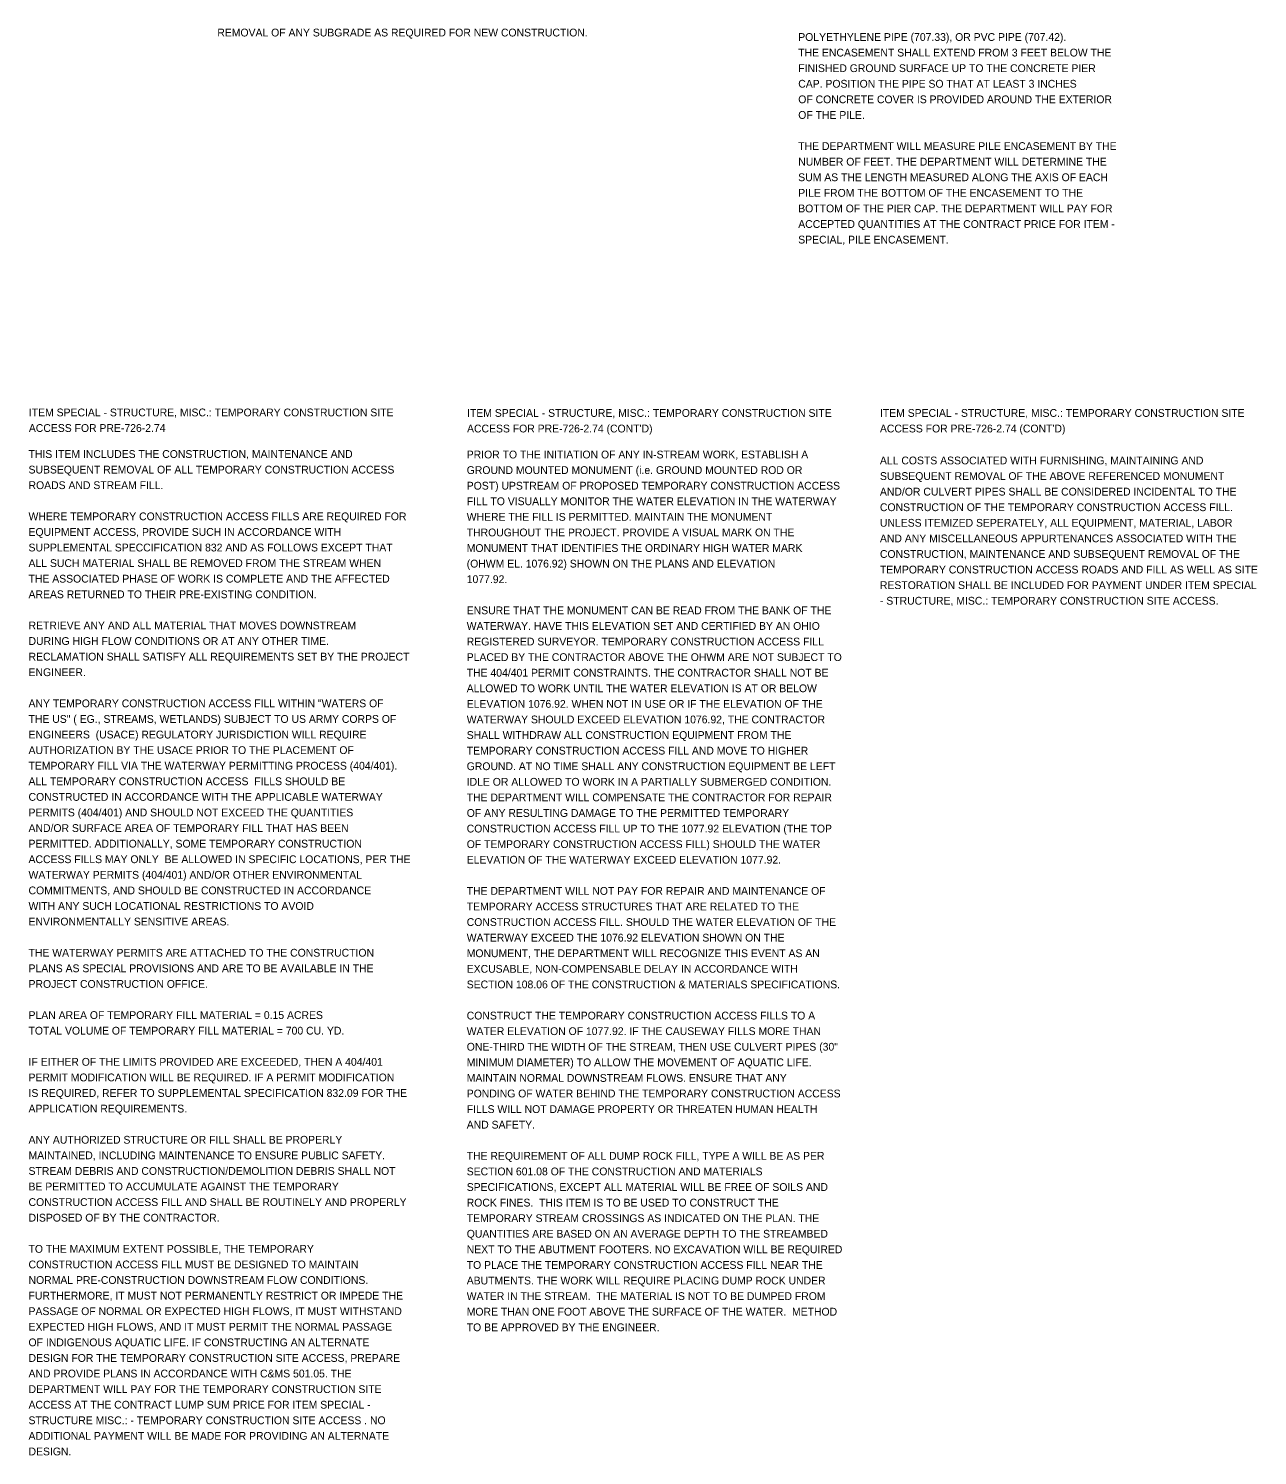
# Model space of a CAD drawing. Extents: x -15 to 144, y -80 to 40.
# Drawn here: x -6.81 to 15.27, y -29.12 to -3.48 of the extents above; entities that cross this region are included whole.
import ezdxf

# ---------------------------------------------------------------- set-up
doc = ezdxf.new("R2010")
doc.units = 0
doc.layers.add('BR_P_Gen_Text', color=7, linetype='Continuous')

msp = doc.modelspace()

# ---------------------------------------------------------------- texts
at = {"layer": 'BR_P_Gen_Text'}
for s, p in [('REMOVAL OF ANY SUBGRADE AS REQUIRED FOR NEW CONSTRUCTION. ', (-3.418, -3.626)), ('POLYETHYLENE PIPE (707.33), OR PVC PIPE (707.42).', (7.022, -3.706)), ('THE ENCASEMENT SHALL EXTEND FROM 3 FEET BELOW THE', (7.022, -3.986)), ('FINISHED GROUND SURFACE UP TO THE CONCRETE PIER', (7.022, -4.266)), ('CAP. POSITION THE PIPE SO THAT AT LEAST 3 INCHES', (7.022, -4.546)), ('OF CONCRETE COVER IS PROVIDED AROUND THE EXTERIOR', (7.022, -4.826)), ('OF THE PILE.', (7.022, -5.106)), ('THE DEPARTMENT WILL MEASURE PILE ENCASEMENT BY THE', (7.022, -5.666)), ('NUMBER OF FEET. THE DEPARTMENT WILL DETERMINE THE', (7.022, -5.946)), ('SUM AS THE LENGTH MEASURED ALONG THE AXIS OF EACH', (7.022, -6.226)), ('PILE FROM THE BOTTOM OF THE ENCASEMENT TO THE', (7.022, -6.506)), ('BOTTOM OF THE PIER CAP. THE DEPARTMENT WILL PAY FOR', (7.022, -6.786)), ('ACCEPTED QUANTITIES AT THE CONTRACT PRICE FOR ITEM -', (7.022, -7.066)), ('SPECIAL, PILE ENCASEMENT.', (7.022, -7.346)), ('ITEM SPECIAL - STRUCTURE, MISC.: TEMPORARY CONSTRUCTION SITE ', (-6.805, -10.451)), ('ITEM SPECIAL - STRUCTURE, MISC.: TEMPORARY CONSTRUCTION SITE ', (1.07, -10.46)), ('ITEM SPECIAL - STRUCTURE, MISC.: TEMPORARY CONSTRUCTION SITE ', (8.49, -10.46)), ('ACCESS FOR PRE-726-2.74', (-6.805, -10.731)), ("ACCESS FOR PRE-726-2.74 (CONT'D) ", (1.07, -10.74)), ("ACCESS FOR PRE-726-2.74 (CONT'D) ", (8.49, -10.74)), ('THIS ITEM INCLUDES THE CONSTRUCTION, MAINTENANCE AND ', (-6.811, -11.198)), ('PRIOR TO THE INITIATION OF ANY IN-STREAM WORK, ESTABLISH A ', (1.064, -11.207)), ('ALL COSTS ASSOCIATED WITH FURNISHING, MAINTAINING AND ', (8.49, -11.314)), ('SUBSEQUENT REMOVAL OF ALL TEMPORARY CONSTRUCTION ACCESS ', (-6.811, -11.478)), ('GROUND MOUNTED MONUMENT (i.e. GROUND MOUNTED ROD OR ', (1.064, -11.487)), ('SUBSEQUENT REMOVAL OF THE ABOVE REFERENCED MONUMENT ', (8.49, -11.594)), ('ROADS AND STREAM FILL. ', (-6.811, -11.758)), ('POST) UPSTREAM OF PROPOSED TEMPORARY CONSTRUCTION ACCESS ', (1.064, -11.767)), ('AND/OR CULVERT PIPES SHALL BE CONSIDERED INCIDENTAL TO THE ', (8.49, -11.874)), ('FILL TO VISUALLY MONITOR THE WATER ELEVATION IN THE WATERWAY ', (1.064, -12.047)), ('CONSTRUCTION OF THE TEMPORARY CONSTRUCTION ACCESS FILL. ', (8.49, -12.154)), ('WHERE TEMPORARY CONSTRUCTION ACCESS FILLS ARE REQUIRED FOR ', (-6.811, -12.318)), ('WHERE THE FILL IS PERMITTED. MAINTAIN THE MONUMENT ', (1.064, -12.327)), ('UNLESS ITEMIZED SEPERATELY, ALL EQUIPMENT, MATERIAL, LABOR ', (8.49, -12.434)), ('EQUIPMENT ACCESS, PROVIDE SUCH IN ACCORDANCE WITH ', (-6.811, -12.598)), ('THROUGHOUT THE PROJECT. PROVIDE A VISUAL MARK ON THE ', (1.064, -12.607)), ('SUPPLEMENTAL SPECCIFICATION 832 AND AS FOLLOWS EXCEPT THAT ', (-6.811, -12.878)), ('MONUMENT THAT IDENTIFIES THE ORDINARY HIGH WATER MARK ', (1.064, -12.887)), ('AND ANY MISCELLANEOUS APPURTENANCES ASSOCIATED WITH THE ', (8.49, -12.714)), ('ALL SUCH MATERIAL SHALL BE REMOVED FROM THE STREAM WHEN ', (-6.811, -13.158)), ('(OHWM EL. 1076.92) SHOWN ON THE PLANS AND ELEVATION', (1.064, -13.167)), ('CONSTRUCTION, MAINTENANCE AND SUBSEQUENT REMOVAL OF THE ', (8.49, -12.994)), ('THE ASSOCIATED PHASE OF WORK IS COMPLETE AND THE AFFECTED ', (-6.811, -13.438)), ('1077.92. ', (1.064, -13.447)), ('TEMPORARY CONSTRUCTION ACCESS ROADS AND FILL AS WELL AS SITE ', (8.49, -13.274)), ('AREAS RETURNED TO THEIR PRE-EXISTING CONDITION.', (-6.811, -13.718)), ('RESTORATION SHALL BE INCLUDED FOR PAYMENT UNDER ITEM SPECIAL ', (8.49, -13.554)), ('- STRUCTURE, MISC.: TEMPORARY CONSTRUCTION SITE ACCESS.', (8.49, -13.834)), ('ENSURE THAT THE MONUMENT CAN BE READ FROM THE BANK OF THE ', (1.064, -14.007)), ('RETRIEVE ANY AND ALL MATERIAL THAT MOVES DOWNSTREAM ', (-6.811, -14.278)), ('WATERWAY. HAVE THIS ELEVATION SET AND CERTIFIED BY AN OHIO ', (1.064, -14.287)), ('DURING HIGH FLOW CONDITIONS OR AT ANY OTHER TIME. ', (-6.811, -14.558)), ('REGISTERED SURVEYOR. TEMPORARY CONSTRUCTION ACCESS FILL ', (1.064, -14.567)), ('RECLAMATION SHALL SATISFY ALL REQUIREMENTS SET BY THE PROJECT ', (-6.811, -14.838)), ('PLACED BY THE CONTRACTOR ABOVE THE OHWM ARE NOT SUBJECT TO ', (1.064, -14.847)), ('ENGINEER.', (-6.811, -15.118)), ('THE 404/401 PERMIT CONSTRAINTS. THE CONTRACTOR SHALL NOT BE ', (1.064, -15.127)), ('ALLOWED TO WORK UNTIL THE WATER ELEVATION IS AT OR BELOW ', (1.064, -15.407)), ('ANY TEMPORARY CONSTRUCTION ACCESS FILL WITHIN "WATERS OF ', (-6.811, -15.678)), ('ELEVATION 1076.92. WHEN NOT IN USE OR IF THE ELEVATION OF THE ', (1.064, -15.687)), ('THE US" ( EG., STREAMS, WETLANDS) SUBJECT TO US ARMY CORPS OF ', (-6.811, -15.958)), ('WATERWAY SHOULD EXCEED ELEVATION 1076.92, THE CONTRACTOR ', (1.064, -15.967)), ('ENGINEERS  (USACE) REGULATORY JURISDICTION WILL REQUIRE ', (-6.811, -16.238)), ('SHALL WITHDRAW ALL CONSTRUCTION EQUIPMENT FROM THE ', (1.064, -16.247)), ('AUTHORIZATION BY THE USACE PRIOR TO THE PLACEMENT OF ', (-6.811, -16.518)), ('TEMPORARY CONSTRUCTION ACCESS FILL AND MOVE TO HIGHER ', (1.064, -16.527)), ('TEMPORARY FILL VIA THE WATERWAY PERMITTING PROCESS (404/401). ', (-6.811, -16.798)), ('GROUND. AT NO TIME SHALL ANY CONSTRUCTION EQUIPMENT BE LEFT ', (1.064, -16.807)), ('ALL TEMPORARY CONSTRUCTION ACCESS  FILLS SHOULD BE ', (-6.811, -17.078)), ('IDLE OR ALLOWED TO WORK IN A PARTIALLY SUBMERGED CONDITION. ', (1.064, -17.087)), ('CONSTRUCTED IN ACCORDANCE WITH THE APPLICABLE WATERWAY ', (-6.811, -17.358)), ('THE DEPARTMENT WILL COMPENSATE THE CONTRACTOR FOR REPAIR ', (1.064, -17.367)), ('PERMITS (404/401) AND SHOULD NOT EXCEED THE QUANTITIES ', (-6.811, -17.638)), ('OF ANY RESULTING DAMAGE TO THE PERMITTED TEMPORARY ', (1.064, -17.647)), ('AND/OR SURFACE AREA OF TEMPORARY FILL THAT HAS BEEN ', (-6.811, -17.918)), ('CONSTRUCTION ACCESS FILL UP TO THE 1077.92 ELEVATION (THE TOP ', (1.064, -17.927)), ('PERMITTED. ADDITIONALLY, SOME TEMPORARY CONSTRUCTION ', (-6.811, -18.198)), ('OF TEMPORARY CONSTRUCTION ACCESS FILL) SHOULD THE WATER ', (1.064, -18.207)), ('ACCESS FILLS MAY ONLY  BE ALLOWED IN SPECIFIC LOCATIONS, PER THE ', (-6.811, -18.478)), ('ELEVATION OF THE WATERWAY EXCEED ELEVATION 1077.92.', (1.064, -18.487)), ('WATERWAY PERMITS (404/401) AND/OR OTHER ENVIRONMENTAL ', (-6.811, -18.758)), ('COMMITMENTS, AND SHOULD BE CONSTRUCTED IN ACCORDANCE ', (-6.811, -19.038)), ('THE DEPARTMENT WILL NOT PAY FOR REPAIR AND MAINTENANCE OF ', (1.064, -19.047)), ('WITH ANY SUCH LOCATIONAL RESTRICTIONS TO AVOID ', (-6.811, -19.318)), ('TEMPORARY ACCESS STRUCTURES THAT ARE RELATED TO THE ', (1.064, -19.327)), ('ENVIRONMENTALLY SENSITIVE AREAS. ', (-6.811, -19.598)), ('CONSTRUCTION ACCESS FILL. SHOULD THE WATER ELEVATION OF THE ', (1.064, -19.607)), ('WATERWAY EXCEED THE 1076.92 ELEVATION SHOWN ON THE ', (1.064, -19.887)), ('THE WATERWAY PERMITS ARE ATTACHED TO THE CONSTRUCTION ', (-6.811, -20.158)), ('MONUMENT, THE DEPARTMENT WILL RECOGNIZE THIS EVENT AS AN ', (1.064, -20.167)), ('PLANS AS SPECIAL PROVISIONS AND ARE TO BE AVAILABLE IN THE ', (-6.811, -20.438)), ('EXCUSABLE, NON-COMPENSABLE DELAY IN ACCORDANCE WITH ', (1.064, -20.447)), ('PROJECT CONSTRUCTION OFFICE. ', (-6.811, -20.718)), ('SECTION 108.06 OF THE CONSTRUCTION & MATERIALS SPECIFICATIONS.', (1.064, -20.727)), ('PLAN AREA OF TEMPORARY FILL MATERIAL = 0.15 ACRES ', (-6.811, -21.278)), ('CONSTRUCT THE TEMPORARY CONSTRUCTION ACCESS FILLS TO A ', (1.064, -21.287)), ('TOTAL VOLUME OF TEMPORARY FILL MATERIAL = 700 CU. YD. ', (-6.811, -21.558)), ('WATER ELEVATION OF 1077.92. IF THE CAUSEWAY FILLS MORE THAN ', (1.064, -21.567)), ('ONE-THIRD THE WIDTH OF THE STREAM, THEN USE CULVERT PIPES (30" ', (1.064, -21.847)), ('IF EITHER OF THE LIMITS PROVIDED ARE EXCEEDED, THEN A 404/401 ', (-6.811, -22.118)), ('MINIMUM DIAMETER) TO ALLOW THE MOVEMENT OF AQUATIC LIFE. ', (1.064, -22.127)), ('PERMIT MODIFICATION WILL BE REQUIRED. IF A PERMIT MODIFICATION ', (-6.811, -22.398)), ('MAINTAIN NORMAL DOWNSTREAM FLOWS. ENSURE THAT ANY ', (1.064, -22.407)), ('IS REQUIRED, REFER TO SUPPLEMENTAL SPECIFICATION 832.09 FOR THE ', (-6.811, -22.678)), ('PONDING OF WATER BEHIND THE TEMPORARY CONSTRUCTION ACCESS ', (1.064, -22.687)), ('APPLICATION REQUIREMENTS.', (-6.811, -22.958)), ('FILLS WILL NOT DAMAGE PROPERTY OR THREATEN HUMAN HEALTH ', (1.064, -22.967)), ('AND SAFETY.', (1.064, -23.247)), ('ANY AUTHORIZED STRUCTURE OR FILL SHALL BE PROPERLY ', (-6.811, -23.518)), ('MAINTAINED, INCLUDING MAINTENANCE TO ENSURE PUBLIC SAFETY. ', (-6.811, -23.798)), ('THE REQUIREMENT OF ALL DUMP ROCK FILL, TYPE A WILL BE AS PER ', (1.064, -23.807)), ('STREAM DEBRIS AND CONSTRUCTION/DEMOLITION DEBRIS SHALL NOT ', (-6.811, -24.078)), ('SECTION 601.08 OF THE CONSTRUCTION AND MATERIALS ', (1.064, -24.087)), ('BE PERMITTED TO ACCUMULATE AGAINST THE TEMPORARY ', (-6.811, -24.358)), ('SPECIFICATIONS, EXCEPT ALL MATERIAL WILL BE FREE OF SOILS AND ', (1.064, -24.367)), ('CONSTRUCTION ACCESS FILL AND SHALL BE ROUTINELY AND PROPERLY ', (-6.811, -24.638)), ('ROCK FINES.  THIS ITEM IS TO BE USED TO CONSTRUCT THE ', (1.064, -24.647)), ('DISPOSED OF BY THE CONTRACTOR.', (-6.811, -24.918)), ('TEMPORARY STREAM CROSSINGS AS INDICATED ON THE PLAN. THE ', (1.064, -24.927)), ('QUANTITIES ARE BASED ON AN AVERAGE DEPTH TO THE STREAMBED ', (1.064, -25.207)), ('TO THE MAXIMUM EXTENT POSSIBLE, THE TEMPORARY ', (-6.811, -25.478)), ('NEXT TO THE ABUTMENT FOOTERS. NO EXCAVATION WILL BE REQUIRED ', (1.064, -25.487)), ('CONSTRUCTION ACCESS FILL MUST BE DESIGNED TO MAINTAIN ', (-6.811, -25.758)), ('TO PLACE THE TEMPORARY CONSTRUCTION ACCESS FILL NEAR THE ', (1.064, -25.767)), ('NORMAL PRE-CONSTRUCTION DOWNSTREAM FLOW CONDITIONS. ', (-6.811, -26.038)), ('ABUTMENTS. THE WORK WILL REQUIRE PLACING DUMP ROCK UNDER ', (1.064, -26.047)), ('FURTHERMORE, IT MUST NOT PERMANENTLY RESTRICT OR IMPEDE THE ', (-6.811, -26.318)), ('WATER IN THE STREAM.  THE MATERIAL IS NOT TO BE DUMPED FROM ', (1.064, -26.327)), ('PASSAGE OF NORMAL OR EXPECTED HIGH FLOWS, IT MUST WITHSTAND ', (-6.811, -26.598)), ('MORE THAN ONE FOOT ABOVE THE SURFACE OF THE WATER.  METHOD ', (1.064, -26.607)), ('EXPECTED HIGH FLOWS, AND IT MUST PERMIT THE NORMAL PASSAGE ', (-6.811, -26.878)), ('TO BE APPROVED BY THE ENGINEER.', (1.064, -26.887)), ('OF INDIGENOUS AQUATIC LIFE. IF CONSTRUCTING AN ALTERNATE ', (-6.811, -27.158)), ('DESIGN FOR THE TEMPORARY CONSTRUCTION SITE ACCESS, PREPARE ', (-6.811, -27.438)), ('AND PROVIDE PLANS IN ACCORDANCE WITH C&MS 501.05. THE ', (-6.811, -27.718)), ('DEPARTMENT WILL PAY FOR THE TEMPORARY CONSTRUCTION SITE ', (-6.811, -27.998)), ('ACCESS AT THE CONTRACT LUMP SUM PRICE FOR ITEM SPECIAL - ', (-6.811, -28.278)), ('STRUCTURE MISC.: - TEMPORARY CONSTRUCTION SITE ACCESS . NO ', (-6.811, -28.558)), ('ADDITIONAL PAYMENT WILL BE MADE FOR PROVIDING AN ALTERNATE ', (-6.811, -28.838)), ('DESIGN. ', (-6.811, -29.118))]:
    msp.add_text(s, height=0.14, dxfattribs=at).set_placement(p)

doc.saveas('drawing.dxf')
